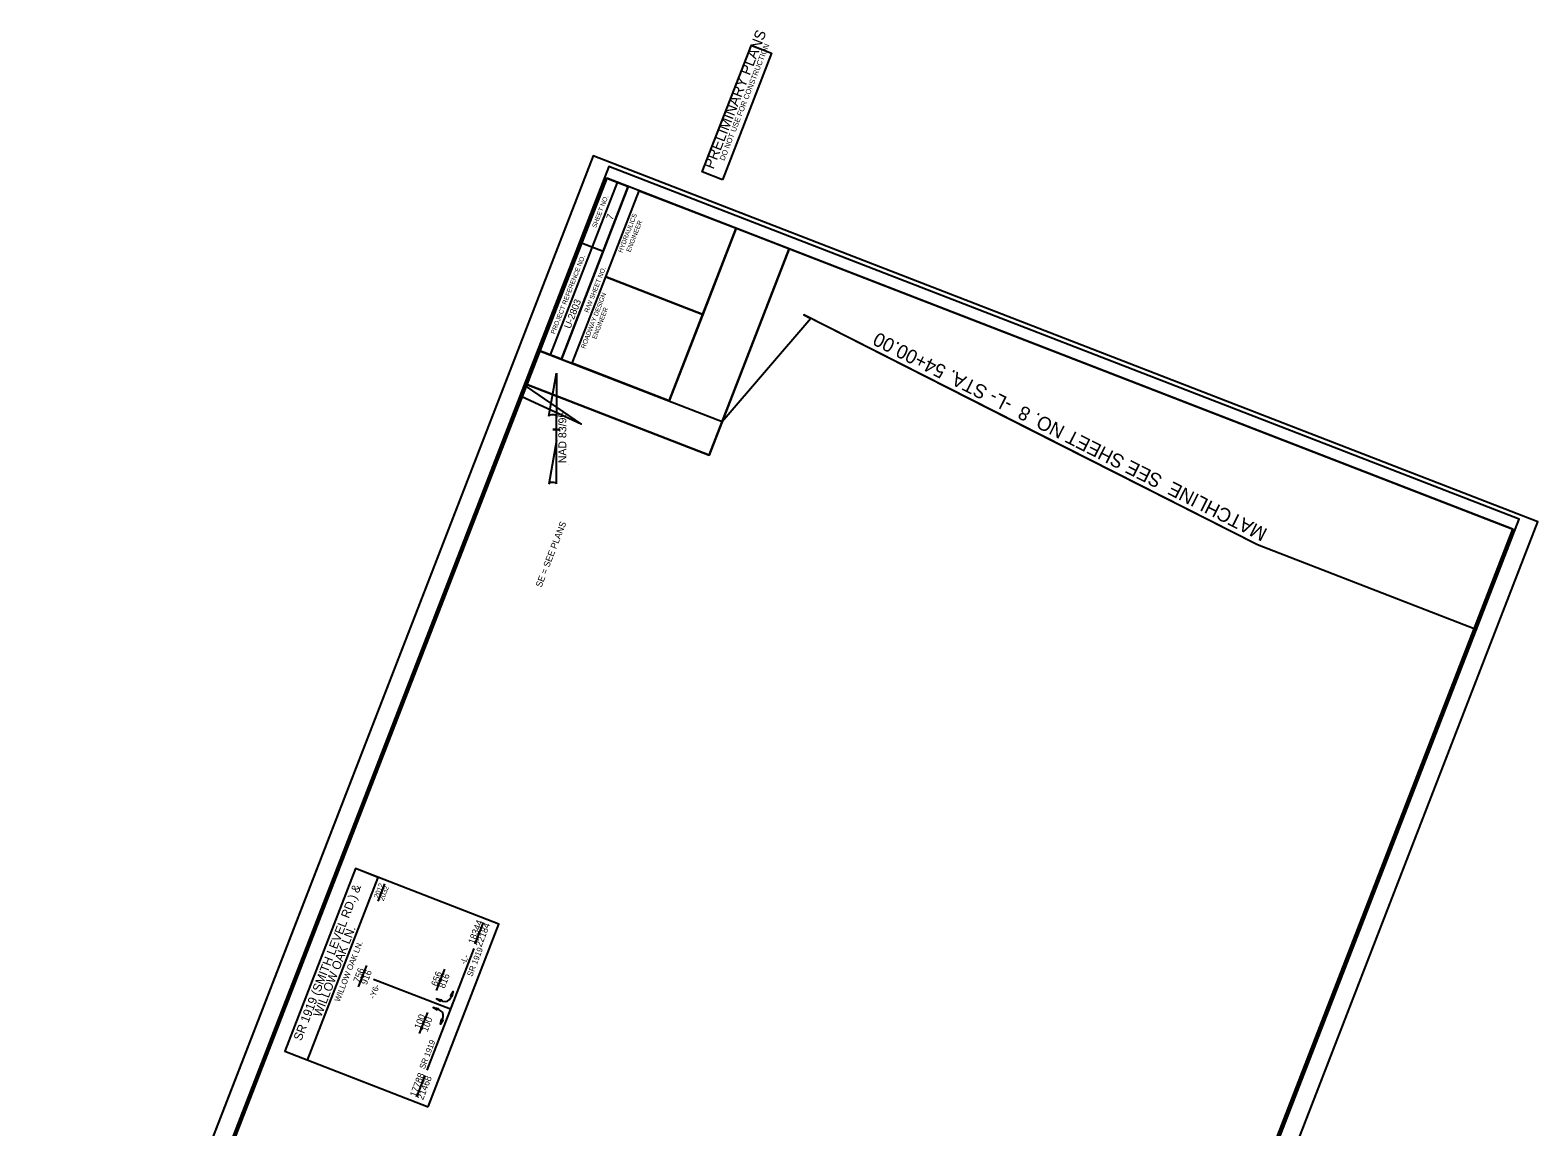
# Model space of a CAD drawing. Extents: x 1976816 to 1978446, y 780470 to 782626.
# Drawn here: x 1976816 to 1978446, y 781441 to 782626 of the extents above; entities that cross this region are included whole.
import ezdxf

# ---------------------------------------------------------------- set-up
doc = ezdxf.new("R2010")
doc.units = 0
for name, color, linetype in [('Matchline', 7, 'Continuous'), ('Matchline Text', 7, 'Continuous'), ('Old_Level_1', 7, 'Continuous'), ('Prop Horizontal Alignment Curve and Spiral Data', 7, 'Continuous'), ('Prop PHM Label Text', 7, 'Continuous'), ('Prop PHM White Label Box', 7, 'Continuous'), ('Sheet Clip Boundary CELL', 7, 'Continuous'), ('Sheet Cutting Line CELL', 7, 'Continuous'), ('Sheet Data Field CELL', 7, 'Continuous'), ('Sheet North Arrow Point CELL', 7, 'Continuous'), ('Sheet Plan CELL', 7, 'Continuous'), ('Sheet Plan Layout CELL', 7, 'Continuous'), ('Sheet Plot Border Inside CELL', 7, 'Continuous'), ('Sheet Plot Border Outside CELL', 7, 'Continuous'), ('Sheet Sticker Preliminary CELL', 7, 'Continuous')]:
    doc.layers.add(name, color=color, linetype=linetype)

msp = doc.modelspace()

# ---------------------------------------------------------------- linework, layer by layer
at = {"layer": 'Matchline'}
msp.add_lwpolyline([(1978142.5, 782069.8), (1977897, 782194.2), (1977652.4, 782318.2)], dxfattribs=at)
at = {"layer": 'Old_Level_1'}
for p, q in [((1977376.9, 782209), (1977385.1, 782255.3)), ((1977385.2, 782255.3), (1977385.1, 782255.3)), ((1977385.2, 782255.3), (1977385.1, 782255.3)), ((1977385.2, 782255.3), (1977385.2, 782207.5)), ((1977385.2, 782182.7), (1977385.2, 782208.9)), ((1977385.2, 782207.5), (1977385.2, 782208.9)), ((1977385.2, 782182.7), (1977376.8, 782135.5)), ((1977381.2, 782194.3), (1977381.1, 782194.3)), ((1977381.2, 782194.3), (1977389.2, 782194.3)), ((1977384.7, 782194.3), (1977381.2, 782194.3)), ((1977385.2, 782135.7), (1977385.2, 782182.7))]:
    msp.add_line(p, q, dxfattribs=at)
for centre, start_param, end_param in [((1977381, 782208.5), 0.216388, 2.908219), ((1977381, 782135.3), 0.201328, 3.141593)]:
    msp.add_ellipse(centre, major_axis=(4.23, -0.03), ratio=0.461098, start_param=start_param, end_param=end_param, dxfattribs=at)
at = {"layer": 'Prop PHM Label Text'}
for p, q in [((1977115.9, 781512.8), (1977192.4, 781710.3)), ((1977192.4, 781710.3), (1977167.9, 781719.8)), ((1977192.3, 781684.7), (1977199.5, 781703.4)), ((1977297.3, 781638.3), (1977306.3, 781661.4)), ((1977245.2, 781501.9), (1977296.2, 781633.5)), ((1977171.2, 781592), (1977180.1, 781615.1)), ((1977270.7, 781567.7), (1977187.4, 781600)), ((1977255.3, 781588.1), (1977264.3, 781611.2)), ((1977261.9, 781576.5), (1977255.3, 781579.1)), ((1977273.4, 781586.8), (1977271, 781580.5)), ((1977237, 781541.4), (1977246, 781564.4)), ((1977258.3, 781567.1), (1977251.7, 781569.7)), ((1977259.9, 781551.8), (1977262.3, 781558.1)), ((1977234.2, 781473.1), (1977243.1, 781496.2))]:
    msp.add_line(p, q, dxfattribs=at)
for points in [[(1977260, 781576.2), (1977255.3, 781579.1), (1977260.7, 781578), (1977259.7, 781577.3)], [(1977272.3, 781581.4), (1977273.4, 781586.8), (1977270.6, 781582.1), (1977271.7, 781582.3)], [(1977256.4, 781566.8), (1977251.7, 781569.7), (1977257.1, 781568.6), (1977256.1, 781568)], [(1977262.7, 781556.5), (1977259.9, 781551.8), (1977260.9, 781557.2), (1977261.6, 781556.2)]]:
    msp.add_lwpolyline(points, close=True, dxfattribs=at)
for centre, start, end in [((1977264.5, 781583), 248.8203, 338.8203), ((1977255.8, 781560.6), 338.8203, 68.8203)]:
    msp.add_arc(centre, 7, start, end, dxfattribs=at)
at = {"layer": 'Prop PHM White Label Box'}
msp.add_lwpolyline([(1977246.4, 781462.2), (1977322.9, 781659.7), (1977167.9, 781719.8), (1977091.4, 781522.3)], close=True, dxfattribs=at)
at = {"layer": 'Sheet Clip Boundary CELL'}
msp.add_lwpolyline([(1977924.5, 780811.8), (1978376.7, 781979.1), (1978142.5, 782069.8), (1977652.4, 782318.2), (1977659.9, 782314.3), (1977564.1, 782202.6), (1977366.9, 782279), (1977352.2, 782241), (1977411.9, 782200.1), (1977347.8, 782229.7), (1976927, 781143.6), (1977040, 781141), (1977039.7, 781120.5), (1977166.5, 781076), (1977684.7, 780893.8)], close=True, dxfattribs=at)
at = {"layer": 'Sheet Cutting Line CELL'}
for p, q in [((1977424.6, 782490.1), (1976816.3, 780920.3)), ((1977837.4, 780524.7), (1978445.6, 782094.5))]:
    msp.add_line(p, q, dxfattribs=at)
at = {"layer": 'Sheet North Arrow Point CELL'}
msp.add_line((1977397.8, 782156.9), (1977397.8, 782156.9), dxfattribs=at)
at = {"layer": 'Sheet Plan CELL'}
for p, q in [((1977378.8, 782275), (1977451.1, 782461.5)), ((1977390.5, 782270.5), (1977462.7, 782457)), ((1977390.5, 782270.5), (1977462.7, 782457)), ((1977412.3, 782396.1), (1977435.7, 782387.1)), ((1977438.3, 782359.3), (1977543.1, 782318.7)), ((1977390.5, 782270.5), (1977402.1, 782266))]:
    msp.add_line(p, q, dxfattribs=at)
for points in [[(1977439.4, 782466.1), (1976897.4, 781067.4), (1977876.5, 780688), (1978418.5, 782086.7)], [(1977367.1, 782279.6), (1977439.4, 782466.1), (1977462.7, 782457), (1977390.5, 782270.5)], [(1977438.3, 782359.3), (1977474.4, 782452.5), (1977579.3, 782411.9), (1977543.2, 782318.6)], [(1977876.5, 780688), (1976897.5, 781067.4), (1977367.1, 782279.6), (1977507, 782225.4), (1977579.3, 782411.9), (1978418.5, 782086.7)], [(1977402.1, 782266), (1977438.3, 782359.3), (1977543.2, 782318.6), (1977507, 782225.4)]]:
    msp.add_lwpolyline(points, close=True, dxfattribs=at)
at = {"layer": 'Sheet Plan Layout CELL'}
for points in [[(1977550.1, 782166.6), (1977636.6, 782389.7), (1977439.4, 782466.1), (1977352.9, 782243)], [(1976897.5, 781067.4), (1977876.5, 780688), (1978418.5, 782086.7), (1977636.6, 782389.7), (1977550.1, 782166.6), (1977352.9, 782243)]]:
    msp.add_lwpolyline(points, close=True, dxfattribs=at)
at = {"layer": 'Sheet Plot Border Inside CELL'}
msp.add_lwpolyline([(1977823.4, 780544), (1978425.3, 782097.5), (1977441.6, 782478.6), (1976839.7, 780925.2)], close=True, dxfattribs=at)
at = {"layer": 'Sheet Plot Border Outside CELL'}
msp.add_lwpolyline([(1977837.4, 780524.7), (1978445.6, 782094.5), (1977424.6, 782490.1), (1976816.3, 780920.3)], close=True, dxfattribs=at)
at = {"layer": 'Sheet Sticker Preliminary CELL'}
msp.add_lwpolyline([(1977564.5, 782464.3), (1977542.6, 782472.8), (1977595.7, 782609.8), (1977617.6, 782601.3)], close=True, dxfattribs=at)

# ---------------------------------------------------------------- texts
at = {"layer": 'Matchline Text'}
msp.add_text('MATCHLINE  SEE SHEET NO. 8  -L- STA. 54+00.00', height=15, rotation=153.1199, dxfattribs=at).set_placement((1978154.4, 782086.3))
at = {"layer": 'Old_Level_1'}
msp.add_text('NAD 83/95', height=8.5, rotation=90, dxfattribs=at).set_placement((1977395.7, 782158))
at = {"layer": 'Prop Horizontal Alignment Curve and Spiral Data'}
msp.add_text('SE = SEE PLANS', height=7, rotation=68.9162, dxfattribs=at).set_placement((1977368.8, 782023.2))
at = {"layer": 'Prop PHM Label Text'}
for s, height, p in [('SR 1919 (SMITH LEVEL RD.) &', 9.414, (1977109.3, 781532.9)), ('2012', 5.4, (1977192.6, 781687.2)), ('2032', 5.4, (1977198.2, 781684.3)), ('18344', 7.2, (1977296, 781637.6)), ('22184', 7.2, (1977303.9, 781634.5)), ('WILLOW OAK LN.', 9.414, (1977130.7, 781558.5)), ('WILLOW OAK LN.', 6.276, (1977150.8, 781575.3)), ('SR 1919', 6.28, (1977294, 781602.6)), ('756', 7.2, (1977171.9, 781595.8)), ('-L-', 6.28, (1977286.7, 781615.7)), ('916', 7.2, (1977180, 781593.6)), ('656', 7.2, (1977255.9, 781592)), ('816', 7.2, (1977264.1, 781589.7)), ('-Y6-', 6.28, (1977188.4, 781578.5)), ('100', 7.2, (1977237.8, 781545.7)), ('100', 7.2, (1977245.6, 781542.7)), ('SR 1919', 6.28, (1977242.5, 781502.6)), ('17788', 7.2, (1977233, 781472.3)), ('21468', 7.2, (1977240.9, 781469.2))]:
    msp.add_text(s, height=height, rotation=68.8292, dxfattribs=at).set_placement(p)
at = {"layer": 'Sheet Data Field CELL'}
for s, p in [('7', (1977445.5, 782420.3)), ('U-2803   ', (1977400, 782302.8))]:
    msp.add_text(s, height=7.5, rotation=68.8203, dxfattribs=at).set_placement(p)
at = {"layer": 'Sheet Plan CELL'}
for s, p in [('SHEET NO.', (1977427.9, 782411.9)), ('HYDRAULICS', (1977456.1, 782385.1)), ('ENGINEER', (1977464.9, 782385.7)), ('PROJECT REFERENCE NO.', (1977383.3, 782297.1)), ('R/W SHEET NO.', (1977419.6, 782320.3)), ('ROADWAY DESIGN', (1977415.9, 782281.4)), ('ENGINEER', (1977428, 782291.7))]:
    msp.add_text(s, height=5, rotation=68.8203, dxfattribs=at).set_placement(p)
at = {"layer": 'Sheet Sticker Preliminary CELL'}
for s, height, p in [('PRELIMINARY PLANS', 11.52, (1977554.6, 782475.1)), ('DO NOT USE FOR CONSTRUCTION', 5.76, (1977566.5, 782484.5))]:
    msp.add_text(s, height=height, rotation=68.8203, dxfattribs=at).set_placement(p)

doc.saveas('drawing.dxf')
